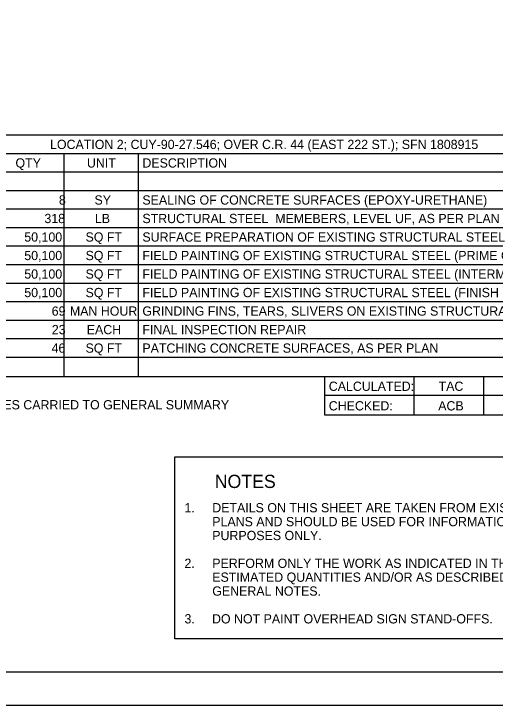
# Model space of a CAD drawing. Extents: x 0 to 34, y 0 to 22.
# Drawn here: x 22.7 to 29.97, y 0 to 10.45 of the extents above; entities that cross this region are included whole.
import ezdxf

# ---------------------------------------------------------------- set-up
doc = ezdxf.new("R2010")
doc.units = 0
for name, color, linetype in [('SH_Border', 7, 'Continuous'), ('SH_Cut_Line', 7, 'Continuous'), ('SH_Text', 7, 'Continuous')]:
    doc.layers.add(name, color=color, linetype=linetype)

msp = doc.modelspace()

# ---------------------------------------------------------------- linework, layer by layer
at = {"layer": 'SH_Border'}
msp.add_lwpolyline([(1.5, 21.5), (33.5, 21.5), (33.5, 0.5), (1.5, 0.5)], close=True, dxfattribs=at)
at = {"layer": 'SH_Cut_Line'}
msp.add_lwpolyline([(0, 0), (34, 0), (34, 22), (0, 22)], close=True, dxfattribs=at)
at = {"layer": 'SH_Text'}
for p, q in [((21.218, 8.624), (31.1, 8.624)), ((21.218, 8.344), (31.1, 8.344)), ((23.458, 8.344), (23.458, 4.968)), ((24.578, 8.344), (24.578, 4.968)), ((21.218, 8.064), (31.1, 8.064)), ((21.218, 7.784), (31.1, 7.784)), ((21.218, 7.504), (31.1, 7.504)), ((21.218, 7.224), (31.1, 7.224)), ((21.218, 6.944), (31.1, 6.944)), ((21.218, 6.664), (31.1, 6.664)), ((21.218, 6.384), (31.1, 6.384)), ((21.218, 6.104), (31.1, 6.104)), ((21.218, 5.824), (31.1, 5.824)), ((21.218, 5.544), (31.1, 5.544)), ((21.218, 5.264), (31.1, 5.264)), ((21.218, 4.968), (31.1, 4.968)), ((27.394, 4.968), (31.1, 4.968)), ((27.394, 4.968), (27.394, 4.391)), ((28.745, 4.968), (28.745, 4.391)), ((29.799, 4.968), (29.799, 4.391)), ((27.394, 4.688), (31.1, 4.688)), ((27.394, 4.391), (31.1, 4.391))]:
    msp.add_line(p, q, dxfattribs=at)
msp.add_lwpolyline([(25.135, 3.753), (31.135, 3.753), (31.135, 1.002), (25.135, 1.002)], close=True, dxfattribs=at)

# ---------------------------------------------------------------- texts
for s, height, p in [('LOCATION 2; CUY-90-27.546; OVER C.R. 44 (EAST 222 ST.); SFN 1808915', 0.14, (23.247, 8.41)), ('QTY', 0.14, (22.725, 8.13)), ('UNIT', 0.14, (23.805, 8.13)), ('DESCRIPTION', 0.14, (24.643, 8.13)), ('                  8', 0.14, (22.445, 7.57)), ('SY', 0.14, (23.919, 7.57)), ('SEALING OF CONCRETE SURFACES (EPOXY-URETHANE)', 0.14, (24.643, 7.57)), ('              318', 0.14, (22.434, 7.29)), ('LB', 0.14, (23.925, 7.29)), ('STRUCTURAL STEEL  MEMEBERS, LEVEL UF, AS PER PLAN', 0.14, (24.643, 7.29)), ('        50,100', 0.14, (22.442, 7.01)), ('SQ FT', 0.14, (23.784, 7.01)), ('SURFACE PREPARATION OF EXISTING STRUCTURAL STEEL', 0.14, (24.643, 7.01)), ('        50,100', 0.14, (22.442, 6.73)), ('SQ FT', 0.14, (23.784, 6.73)), ('FIELD PAINTING OF EXISTING STRUCTURAL STEEL (PRIME COAT)', 0.14, (24.643, 6.73)), ('        50,100', 0.14, (22.442, 6.45)), ('SQ FT', 0.14, (23.784, 6.45)), ('FIELD PAINTING OF EXISTING STRUCTURAL STEEL (INTERMEDIATE COAT)', 0.14, (24.643, 6.45)), ('        50,100', 0.14, (22.442, 6.17)), ('SQ FT', 0.14, (23.784, 6.17)), ('FIELD PAINTING OF EXISTING STRUCTURAL STEEL (FINISH COAT)', 0.14, (24.643, 6.17)), ('                69', 0.14, (22.44, 5.89)), ('MAN HOUR', 0.14, (23.547, 5.89)), ('GRINDING FINS, TEARS, SLIVERS ON EXISTING STRUCTURAL STEEL', 0.14, (24.643, 5.89)), ('                23', 0.14, (22.442, 5.61)), ('EACH', 0.14, (23.802, 5.61)), ('FINAL INSPECTION REPAIR', 0.14, (24.643, 5.61)), ('                46', 0.14, (22.438, 5.33)), ('SQ FT', 0.14, (23.784, 5.33)), ('PATCHING CONCRETE SURFACES, AS PER PLAN', 0.14, (24.643, 5.33)), ('CALCULATED:', 0.14, (27.46, 4.753)), ('TAC', 0.14, (29.12, 4.753)), ('ALL QUANTITIES CARRIED TO GENERAL SUMMARY', 0.14, (21.283, 4.473)), ('CHECKED:', 0.14, (27.46, 4.457)), ('ACB', 0.14, (29.114, 4.457)), ('NOTES', 0.2, (25.737, 3.284)), ('1. ', 0.14, (25.279, 2.916)), ('DETAILS ON THIS SHEET ARE TAKEN FROM EXISTING ', 0.14, (25.699, 2.916)), ('PLANS AND SHOULD BE USED FOR INFORMATION ', 0.14, (25.699, 2.706)), ('PURPOSES ONLY.', 0.14, (25.699, 2.496)), ('2.', 0.14, (25.279, 2.076)), ('PERFORM ONLY THE WORK AS INDICATED IN THE ', 0.14, (25.699, 2.076)), ('ESTIMATED QUANTITIES AND/OR AS DESCRIBED IN THE ', 0.14, (25.699, 1.866)), ('GENERAL NOTES.', 0.14, (25.699, 1.656)), ('3.     DO NOT PAINT OVERHEAD SIGN STAND-OFFS.', 0.14, (25.279, 1.236))]:
    msp.add_text(s, height=height, dxfattribs=at).set_placement(p)

doc.saveas('drawing.dxf')
